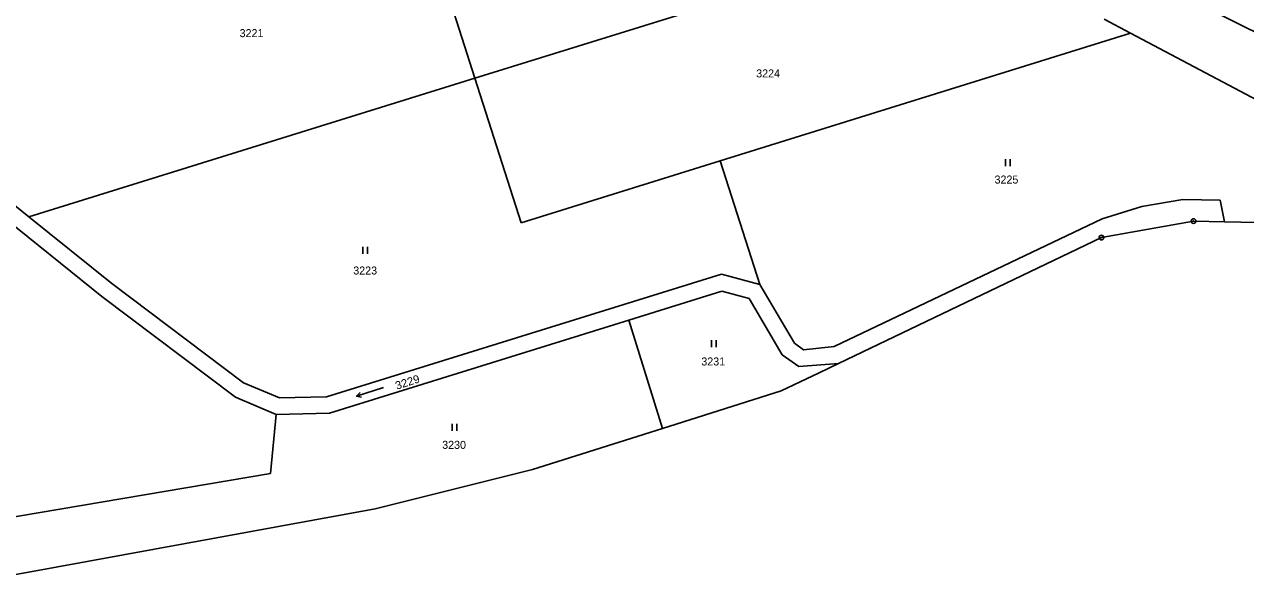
# Model space of a CAD drawing. Extents: x -618848 to -615803, y -1044450 to -1042254.
# Drawn here: x -616873.5 to -616614, y -1043823.3 to -1043703.1 of the extents above; entities that cross this region are included whole.
import ezdxf

# ---------------------------------------------------------------- set-up
doc = ezdxf.new("R2010")
doc.units = 0
doc.header["$LTSCALE"] = 0.68
for name, color, linetype, lineweight in [('1', 7, 'Continuous', 25), ('3', 7, 'Continuous', 25), ('8', 7, 'Continuous', 25)]:
    doc.layers.add(name, color=color, linetype=linetype, lineweight=lineweight)
doc.layers.add('2', color=7, linetype='Continuous')

msp = doc.modelspace()

# ---------------------------------------------------------------- linework, layer by layer
at = {"layer": '1'}
for p, q in [((-616794.99, -1043660.36), (-616777.72, -1043714.52)), ((-616777.72, -1043714.52), (-616675.3, -1043682.65)), ((-616602.71, -1043709.3), (-616637.53, -1043691.9)), ((-616644.04, -1043701.98), (-616638.41, -1043704.95)), ((-616638.41, -1043704.95), (-616725.59, -1043732.08)), ((-616638.41, -1043704.95), (-616608.97, -1043720.5)), ((-616777.72, -1043714.52), (-616872.49, -1043744.01)), ((-616767.92, -1043745.25), (-616777.72, -1043714.52)), ((-616725.59, -1043732.08), (-616767.92, -1043745.25)), ((-616717.21, -1043758.37), (-616725.59, -1043732.08)), ((-616884.69, -1043738.67), (-616857.04, -1043760.94)), ((-616872.49, -1043744.01), (-616877.02, -1043740.36)), ((-616635.98, -1043741.83), (-616627.27, -1043740.33)), ((-616627.27, -1043740.33), (-616619.36, -1043740.45)), ((-616619.36, -1043740.45), (-616618.47, -1043745.04)), ((-616872.49, -1043744.01), (-616854.9, -1043758.17)), ((-616644.44, -1043744.46), (-616635.98, -1043741.83)), ((-616701.37, -1043771.57), (-616644.44, -1043744.46)), ((-616644.61, -1043748.42), (-616625.02, -1043744.91)), ((-616625.02, -1043744.91), (-616618.47, -1043745.04)), ((-616618.47, -1043745.04), (-616604.5, -1043745.33)), ((-616700.46, -1043775.21), (-616644.61, -1043748.42)), ((-616809.24, -1043782.29), (-616725.33, -1043756.19)), ((-616725.33, -1043756.19), (-616717.21, -1043758.37)), ((-616854.9, -1043758.17), (-616826.88, -1043779.29)), ((-616717.21, -1043758.37), (-616709.84, -1043770.91)), ((-616857.04, -1043760.94), (-616828.62, -1043782.36)), ((-616745.05, -1043765.99), (-616725.28, -1043759.84)), ((-616725.28, -1043759.84), (-616719.49, -1043761.4)), ((-616719.49, -1043761.4), (-616712.46, -1043773.36)), ((-616808.65, -1043785.77), (-616745.05, -1043765.99)), ((-616745.05, -1043765.99), (-616737.88, -1043789.03)), ((-616709.84, -1043770.91), (-616707.89, -1043772.27)), ((-616707.89, -1043772.27), (-616701.37, -1043771.57)), ((-616712.46, -1043773.36), (-616708.88, -1043775.85)), ((-616712.62, -1043781.04), (-616704.55, -1043777.17)), ((-616708.88, -1043775.85), (-616700.46, -1043775.21)), ((-616704.55, -1043777.17), (-616700.46, -1043775.21)), ((-616826.88, -1043779.29), (-616819.25, -1043782.54)), ((-616828.62, -1043782.36), (-616819.96, -1043786.05)), ((-616819.25, -1043782.54), (-616809.24, -1043782.29)), ((-616737.88, -1043789.03), (-616712.62, -1043781.04)), ((-616819.96, -1043786.05), (-616821.14, -1043798.62)), ((-616819.96, -1043786.05), (-616808.65, -1043785.77)), ((-616765.51, -1043797.77), (-616737.88, -1043789.03)), ((-616798.9, -1043806.12), (-616765.51, -1043797.77)), ((-616821.14, -1043798.62), (-616893.15, -1043810.82)), ((-616872.98, -1043819.7), (-616798.9, -1043806.12)), ((-616894.33, -1043823.31), (-616872.98, -1043819.7))]:
    msp.add_line(p, q, dxfattribs=at)
at = {"layer": '3'}
for p, q in [((-616664.981, -1043733.21), (-616664.981, -1043731.71)), ((-616663.98, -1043733.21), (-616663.98, -1043731.71)), ((-616801.551, -1043751.88), (-616801.551, -1043750.38)), ((-616800.55, -1043751.88), (-616800.55, -1043750.38)), ((-616727.441, -1043771.75), (-616727.441, -1043770.25)), ((-616726.44, -1043771.75), (-616726.44, -1043770.25)), ((-616802.892, -1043782.184), (-616802.118, -1043781.405)), ((-616782.551, -1043789.53), (-616782.551, -1043788.03)), ((-616781.55, -1043789.53), (-616781.55, -1043788.03))]:
    msp.add_line(p, q, dxfattribs=at)
msp.add_lwpolyline([(-616797.186, -1043780.33), (-616802.892, -1043782.184), (-616801.808, -1043782.359)], dxfattribs=at)
at = {"layer": '8'}
for centre, radius in [((-616625.02, -1043744.9099), 0.5), ((-616625.02, -1043744.9099), 0.0303), ((-616644.61, -1043748.4199), 0.5), ((-616644.61, -1043748.4199), 0.0303)]:
    msp.add_circle(centre, radius, dxfattribs=at)

# ---------------------------------------------------------------- texts
at = {"layer": '2'}
for s, p in [('3221', (-616827.73, -1043705.775)), ('3224', (-616717.96, -1043714.345)), ('3225', (-616667.31, -1043736.925)), ('3223', (-616803.58, -1043756.275)), ('3231', (-616729.62, -1043775.625)), ('3230', (-616784.69, -1043793.365))]:
    msp.add_text(s, height=1.7, dxfattribs=at).set_placement(p)
at = {"layer": '2', "width": 1.05}
msp.add_text('3229', height=1.7, rotation=18, dxfattribs=at).set_placement((-616794.338, -1043780.804))

doc.saveas('drawing.dxf')
